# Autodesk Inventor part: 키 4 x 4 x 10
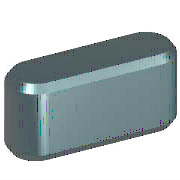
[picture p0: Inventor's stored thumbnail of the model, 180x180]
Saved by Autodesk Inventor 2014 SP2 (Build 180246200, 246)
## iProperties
IsCustomPart: 1
Created: 2012-02
Part Number: 키 4 x 4 x 10
Material: 강철, 연강
Description: 키 및 해당 키홈
Document SubType Name: Modeling
Standard: KS B 1311
Designer: test
Standards Organization: KS
Language: ko-KR
Size Designation: 4 x 4 x 10
Categories: <MemberInstance><Categories><Category DisplayName="샤프트 부품" InternalName="7f7aeb1f-a693-4053-b835-cee3144e0d98" Mnemonic="SHFT"><Category DisplayName="키" Interna
Density: 1 g/cm^3
Appearance: 강철
Author: test
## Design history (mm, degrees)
workplane "Work Plane1"
workplane "Work Plane2"
sketch "스케치1"
  geometry: L1 (2, 2)-(8, 2); L2 (8, -2)-(2, -2); L3 (0, 9.4)-(0, -7.4) reference; L4 (-5, 0)-(30, 0) reference; L5 (10, 0)-(10, 7); A1 r 2 centre (2, 0) between (2, 2) and (2, -2); A2 r 2 centre (8, 0) between (8, -2) and (8, 2)
  constraints: 6 end point, 5 point on circle, 4 tangent, 3 point on line, 2 centre point, 1 horizontal, 1 parallel, 1 perpendicular
  dimensions: "d0" = 2 radius of A1 (= 0.5 x PB); "d13" = 2 radius of A2 (= 0.5 x PB); "d14" = 10 distance between parallel lines of L5 L3 (= NLG)
extrude "본체1" new body sketch "스케치1" taper "d3" = 0 deg; stored distance "d4" = 10
workplane "Work Plane3"
body "Solid1"
chamfer "모따기1" distance "d8" = 0.25 (= PHH); stored, may be unused: second distance "d9" = 0.25 (= PHH), angle "d15" = 45 deg
other parameters: "d1" = -2.5 (= -PNT), "d2" = 1.5 (= PH - PNT), "NLG" = 10 [user parameter; used in 3 equation terms], "PB" = 4 [user parameter; used in 2 equation terms], "PNT" = 2.5 [user parameter; used in 2 equation terms], "PH" = 4 [user parameter; used in 1 equation term], "PHH" = 0.25 [user parameter; used in 2 equation terms], "d10" = 0, "d16" = 0, "d17" = 0, "d18" = 0, "WDMAX" = 12 [user parameter], "RR" = 0.08 [user parameter], "PUEB" = 1.8 [user parameter]
